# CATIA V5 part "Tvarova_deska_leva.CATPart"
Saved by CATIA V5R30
Part number: Tvarova_deska_leva
Definition: F 50_346446_46_1730_1
Nomenclature: F 50_346446_46_1730_1
Source: Unknown
Description: PART--DESC
Bounding box of the stored display mesh (mm): x -223 to 223, y -173 to 173, z -92 to 0
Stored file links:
  E:\Bakalarka\Model\Forma_v7\Tvarova_deska_leva.CATPart
  E:\Bakalarka\Model\Forma_v7\Vyhazovaci_cast.CATProduct
  E:\Bakalarka\Model\Sestava_formy_1\Forma_Vyhazovaci_cast.CATPart
  E:\Bakalarka\Model\Chyba catie 2\Forma_Vyhazovaci_cast.CATPart
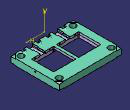
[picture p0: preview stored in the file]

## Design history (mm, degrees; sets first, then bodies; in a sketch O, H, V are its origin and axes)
Body1 "MANIFOLD_SOLID_BREP #4123" (main body)
  Solid1: solid without history
  DatumCurve1 to DatumCurve16
  Sketch1 on face of Solid1, origin (0, 0, -46), H (1, 0, 0), V (0, 1, 0)
    projected line E1 (170, 75) -> (170, -75) from edge of DatumCurve1
    projected arc E2 centre (165, -75) radius 5 from (165, -80) to (170, -75) ccw from edge of DatumCurve2
    projected line E3 (165, -80) -> (15, -80) from edge of DatumCurve3
    projected arc E4 centre (15, -75) radius 5 from (10, -75) to (15, -80) ccw from edge of DatumCurve4
    projected line E5 (10, -75) -> (10, 75) from edge of DatumCurve5
    projected arc E6 centre (15, 75) radius 5 from (15, 80) to (10, 75) ccw from edge of DatumCurve6
    projected line E7 (15, 80) -> (165, 80) from edge of DatumCurve7
    projected arc E8 centre (165, 75) radius 5 from (170, 75) to (165, 80) ccw from edge of DatumCurve8
    projected line E9 (-165, 80) -> (-15, 80) from edge of DatumCurve9
    projected arc E10 centre (-15, 75) radius 5 from (-10, 75) to (-15, 80) ccw from edge of DatumCurve10
    projected line E11 (-10, 75) -> (-10, -75) from edge of DatumCurve11
    projected arc E12 centre (-15, -75) radius 5 from (-15, -80) to (-10, -75) ccw from edge of DatumCurve12
    projected line E13 (-15, -80) -> (-165, -80) from edge of DatumCurve13
    projected arc E14 centre (-165, -75) radius 5 from (-170, -75) to (-165, -80) ccw from edge of DatumCurve14
    projected line E15 (-170, -75) -> (-170, 75) from edge of DatumCurve15
    projected arc E16 centre (-165, 75) radius 5 from (-165, 80) to (-170, 75) ccw from edge of DatumCurve16
  Pocket1: profile Sketch1, direction (0, 0, -1), length 16
  DatumSurface1
  DatumSurface2
  DatumCurve17 to DatumCurve30
  Sketch2 on face of Solid1, origin (0, 0, -92), H (1, 0, 0), V (0, -1, 0)
    projected arc E1 centre (5, -85) radius 5 from (0, -85) to (5, -90) ccw from edge of DatumCurve17
    projected line E2 (5, -90) -> (175, -90) from edge of DatumCurve18
    projected arc E3 centre (175, -85) radius 5 from (175, -90) to (180, -85) ccw from edge of DatumCurve19
    projected line E4 (180, -85) -> (180, 85) from edge of DatumCurve20
    projected arc E5 centre (175, 85) radius 5 from (180, 85) to (175, 90) ccw from edge of DatumCurve21
    projected line E6 (175, 90) -> (5, 90) from edge of DatumCurve22
    projected arc E7 centre (5, 85) radius 5 from (5, 90) to (0, 85) ccw from edge of DatumCurve23
    projected arc E8 centre (-5, 85) radius 5 from (0, 85) to (-5, 90) ccw from edge of DatumCurve24
    projected line E9 (-5, 90) -> (-175, 90) from edge of DatumCurve25
    projected arc E10 centre (-175, 85) radius 5 from (-175, 90) to (-180, 85) ccw from edge of DatumCurve26
    projected line E11 (-180, 85) -> (-180, -85) from edge of DatumCurve27
    projected arc E12 centre (-175, -85) radius 5 from (-180, -85) to (-175, -90) ccw from edge of DatumCurve28
    projected line E13 (-175, -90) -> (-5, -90) from edge of DatumCurve29
    projected arc E14 centre (-5, -85) radius 5 from (-5, -90) to (0, -85) ccw from edge of DatumCurve30
  Pocket2: profile Sketch2, direction (0, 0, 1), length 30
  Fillet1: radius 1, on edge [face of Pocket2 from Sketch2.E1 | face of Pocket2 from Sketch2.E14]; edge [face of Pocket2 from Sketch2.E8 | face of Pocket2 from Sketch2.E7]
  Body2 "Result of __DrillHole"
    Solid2: linked copy from another document
  Assemble1 "DrillHoleEjector_E1710_2.1": tool Body2
  Body3 "Result of __DrillHole"
    Solid3: linked copy from another document
  Assemble2 "DrillHoleEjector_E1710_3.1": tool Body3
  Body4 "Result of __DrillHole"
    Solid4: linked copy from another document
  Assemble3 "DrillHoleEjector_E1710_4.1": tool Body4
  Body5 "Result of __DrillHole"
    Solid5: linked copy from another document
  Assemble4 "DrillHoleEjector_E1710_5.1": tool Body5
  Body6 "Result of __DrillHole"
    Solid6: linked copy from another document
  Assemble5 "DrillHoleEjector_E1710_6.1": tool Body6
  Body7 "Result of __DrillHole"
    Solid7: linked copy from another document
  Assemble6 "DrillHoleEjector_E1710_1.1": tool Body7
  Body8 "Result of __DrillHole"
    Solid8: linked copy from another document
  Assemble7 "DrillHoleEjector_E1710_13.1": tool Body8
  Body9 "Result of __DrillHole"
    Solid9: linked copy from another document
  Assemble8 "DrillHoleEjector_E1710_14.1": tool Body9
  Body10 "Result of __DrillHole"
    Solid10: linked copy from another document
  Assemble9 "DrillHoleEjector_E1710_15.1": tool Body10
  Body11 "Result of __DrillHole"
    Solid11: linked copy from another document
  Assemble10 "DrillHoleEjector_E1710_16.1": tool Body11
  Body12 "Result of __DrillHole"
    Solid12: linked copy from another document
  Assemble11 "DrillHoleEjector_E1710_17.1": tool Body12
  Body13 "Result of __DrillHole"
    Solid13: linked copy from another document
  Assemble12 "DrillHoleEjector_E1710_18.1": tool Body13
  Body14 "Result of __DrillHole"
    Solid14: linked copy from another document
  Assemble13 "DrillHoleEjector_E1710_19.1": tool Body14
  Body15 "Result of __DrillHole"
    Solid15: linked copy from another document
  Assemble14 "DrillHoleEjector_E1710_20.1": tool Body15
  Body16 "Result of __DrillHole"
    Solid16: linked copy from another document
  Assemble15 "DrillHoleEjector_E1710_21.1": tool Body16
  Body17 "Result of __DrillHole"
    Solid17: linked copy from another document
  Assemble16 "DrillHoleEjector_E1710_23.1": tool Body17
  Body18 "Result of __DrillHole"
    Solid18: linked copy from another document
  Assemble17 "DrillHoleEjector_E1710_24.1": tool Body18
  Body19 "Result of __DrillHole"
    Solid19: linked copy from another document
  Assemble18 "DrillHoleEjector_E1710_25.1": tool Body19
  Body20 "Result of __DrillHole"
    Solid20: linked copy from another document
  Assemble19 "DrillHoleEjector_E1710_26.1": tool Body20
  Body21 "Result of __DrillHole"
    Solid21: linked copy from another document
  Assemble20 "DrillHoleEjector_E1710_27.1": tool Body21
  Body22 "Result of __DrillHole"
    Solid22: linked copy from another document
  Assemble21 "DrillHoleEjector_E1710_28.1": tool Body22
  Body23 "Result of __DrillHole"
    Solid23: linked copy from another document
  Assemble22 "DrillHoleEjector_E1710_29.1": tool Body23
  DatumCurve31 to DatumCurve38
  DatumSurface3
  DatumCurve39
  DatumSurface4
  DatumCurve40 to DatumCurve42
  DatumSurface5
  DatumCurve43 to DatumCurve49
  DatumSurface6
  DatumCurve50 to DatumCurve53
  DatumSurface7
  DatumCurve54
  Sketch3 on face of DatumSurface7, origin (0, 0, -128), H (1, 0, 0), V (0, 1, 0)
    construction line L1 (90.0667, -159.3771) -> (90.0667, -123.0944)
    line L2 (82.0323, -159.3771) -> (82.0323, -123.0944)
    line L3 (98.1012, -123.0944) -> (98.1012, -159.3771)
    arc A1 centre (90.0667, -123.0944) radius 8.0344 from (82.0323, -123.0944) to (98.1012, -123.0944) cw
    arc A2 centre (90.0667, -159.3771) radius 8.0344 from (98.1012, -159.3771) to (82.0323, -159.3771) cw
    construction line L4 (-89.9571, -153.2014) -> (-89.9571, -123.4032)
    line L5 (-99.1963, -153.2014) -> (-99.1963, -123.4032)
    line L6 (-80.718, -123.4032) -> (-80.718, -153.2014)
    arc A3 centre (-89.9571, -123.4032) radius 9.2392 from (-99.1963, -123.4032) to (-80.718, -123.4032) cw
    arc A4 centre (-89.9571, -153.2014) radius 9.2392 from (-80.718, -153.2014) to (-99.1963, -153.2014) cw
    reference projected line E1 (223, 173) -> (223, -173) from edge of DatumCurve54
    distance L1 L2 = 8.0344
    distance L4 L5 = 9.2392
    distance L1 E1 = 132.9333
    vertical: L1 V, L4 V
    tangency: A1 L2, A2 L2, A1 L3, A2 L3, A3 L5, A4 L5, A3 L6, A4 L6
  DatumCurve55
  DatumCurve56
  DatumSurface8
  DatumCurve57 to DatumCurve76
  DatumSurface9
  DatumCurve77
  DatumSurface10 to DatumSurface13
  DatumCurve78 to DatumCurve81
  Body24 "MANIFOLD_SOLID_BREP #197"
    Solid24: solid without history
  Remove1: tool Body24
  DatumCurve82
  DatumCurve83
  Sketch4 on face of Solid1, origin (0, -173, 0), H (1, 0, 0), V (0, 0, 1)
    point P1 (143.5, -54)
    reference projected line E1 (-223, -46) -> (189, -46) from edge [face of Solid1 | face of Solid1]
    reference projected line E2 (223, -88) -> (223, -50) from edge [face of Solid1 | face of Solid1]
    distance P1 E1 = 8
    distance P1 E2 = 79.5
  DatumCurve84 to DatumCurve91
  Sketch5 on face of Solid1, origin (0, 0, -92), H (1, 0, 0), V (0, -1, 0)
    point P17 (140, 137)
    point P18 (-140, 137)
    point P19 (-140, -137)
    point P20 (140, -137)
    reference projected line E9 (223, -139) -> (223, 139) from edge [face of Solid1 | face of Solid1]
    reference projected line E10 (-189, -173) -> (189, -173) from edge [face of Solid1 | face of Solid1]
    reference projected line E11 (-223, 139) -> (-223, -139) from edge [face of Solid1 | face of Solid1]
    reference projected line E12 (189, 173) -> (-189, 173) from edge [face of Solid1 | face of Solid1]
    distance P20 E9 = 83
    distance P20 E10 = 36
    distance P19 E10 = 36
    distance P19 E11 = 83
    distance P18 E11 = 83
    distance P18 E12 = 36
    distance P17 E12 = 36
    distance P17 E9 = 83
  Sketch6 on face of Solid1, origin (143.5, -173, -54), H (1, 0, 0), V (0, 0, 1)
    point P1 (0, 0)
    reference projected point E1 (0, 0) from Sketch4.P1
    coincidence: E1 P1
  Hole1: placed by Sketch6, at (143.5, -173, -54) direction (0, 1, 0), diameter 10, depth 150, V-bottom angle 120
  DatumSurface14
  Sketch7 on face of Solid1, origin (0, -173, 0), H (1, 0, 0), V (0, 0, 1)
    point P1 (35, -54)
    point P2 (-36.5, -54)
    point P3 (-145, -54)
    reference projected line E1 (-223, -88) -> (-223, -46) from edge [face of Solid1 | face of Solid1]
    reference intersected curve E2 from face of DatumSurface14
    reference projected line E3 (-223, -46) -> (189, -46) from edge [face of Solid1 | face of Solid1]
    distance P3 E1 = 78
    distance P2 P3 = 108.5
    distance P3 E2 = 8
    distance P2 E3 = 8
    distance P1 E3 = 8
    distance P2 P1 = 71.5
  Sketch8 on face of Solid1, origin (35, -173, -54), H (1, 0, 0), V (0, 0, 1)
    point P1 (0, 0)
    reference projected point E1 (0, 0) from Sketch7.P1
    coincidence: E1 P1
  Hole2: placed by Sketch8, at (35, -173, -54) direction (0, 1, 0), diameter 10, depth 150, V-bottom angle 120
  Sketch9 on face of Solid1, origin (-36.5, -173, -54), H (1, 0, 0), V (0, 0, 1)
    point P1 (0, 0)
    reference projected point E1 (0, 0) from Sketch7.P2
    coincidence: E1 P1
  Hole3: placed by Sketch9, at (-36.5, -173, -54) direction (0, 1, 0), diameter 10, depth 150, V-bottom angle 120
  Sketch10 on face of Solid1, origin (-145, -173, -54), H (1, 0, 0), V (0, 0, 1)
    point P1 (0, 0)
    reference projected point E1 (0, 0) from Sketch7.P3
    coincidence: E1 P1
  Hole4: placed by Sketch10, at (-145, -173, -54) direction (0, 1, 0), diameter 10, depth 150, V-bottom angle 120
  Sketch11 on face of Solid1, origin (143.5, -173, -54), H (1, 0, 0), V (0, 0, 1)
    point P1 (0, 0)
    reference projected point E1 (0, 0) from Sketch4.P1
    coincidence: E1 P1
  Hole5: placed by Sketch11, at (143.5, -173, -54) direction (0, 1, 0), diameter 12.376, depth 12, V-bottom angle 120, threaded "M14x1.5", thread diameter 14, thread depth 10, pitch 1.5
  Sketch12 on face of Solid1, origin (35, -173, -54), H (1, 0, 0), V (0, 0, 1)
    point P1 (0, 0)
    reference projected point E1 (0, 0) from Sketch7.P1
    coincidence: E1 P1
  Hole6: placed by Sketch12, at (35, -173, -54) direction (0, 1, 0), diameter 12.376, depth 12, V-bottom angle 120, threaded "M14x1.5", thread diameter 14, thread depth 10, pitch 1.5
  Sketch13 on face of Solid1, origin (-36.5, -173, -54), H (1, 0, 0), V (0, 0, 1)
    point P1 (0, 0)
    reference projected point E1 (0, 0) from Sketch7.P2
    coincidence: E1 P1
  Hole7: placed by Sketch13, at (-36.5, -173, -54) direction (0, 1, 0), diameter 12.376, depth 12, V-bottom angle 120, threaded "M14x1.5", thread diameter 14, thread depth 10, pitch 1.5
  Sketch14 on face of Solid1, origin (-145, -173, -54), H (1, 0, 0), V (0, 0, 1)
    point P1 (0, 0)
    reference projected point E1 (0, 0) from Sketch7.P3
    coincidence: E1 P1
  Hole8: placed by Sketch14, at (-145, -173, -54) direction (0, 1, 0), diameter 12.376, depth 12, V-bottom angle 120, threaded "M14x1.5", thread diameter 14, thread depth 10, pitch 1.5
  DatumCurve92
  Sketch15 on face of Solid1, origin (0, -173, 0), H (1, 0, 0), V (0, 0, 1)
    arc A1 centre (143.5, -54) radius 12.5 from (131, -54) to (156, -54) ccw
    arc A2 centre (35, -54) radius 12.5 from (22.5, -54) to (47.5, -54) ccw
    arc A3 centre (-36.5, -54) radius 12.5 from (-49, -54) to (-24, -54) ccw
    arc A4 centre (-145.5, -54) radius 12.5 from (-158, -54) to (-133, -54) ccw
    reference projected line E1 (223, -88) -> (223, -50) from edge [face of Solid1 | face of Solid1]
    reference projected line E2 (189, -92) -> (-189, -92) from edge [face of Solid1 | face of Solid1]
    reference projected line E3 (-223, -92) -> (223, -92) from edge of DatumCurve92
    projected line E4 (-223, -46) -> (189, -46) from edge [face of Solid1 | face of Solid1]
    projected line E5 (-158, -46) -> (-133, -46) from edge [face of Solid1 | face of Solid1]
    projected line E6 (-49, -46) -> (-24, -46) from edge [face of Solid1 | face of Solid1]
    projected line E7 (22.5, -46) -> (47.5, -46) from edge [face of Solid1 | face of Solid1]
    projected line E8 (131, -46) -> (156, -46) from edge [face of Solid1 | face of Solid1]
    line L1 (156, -54) -> (156, -46)
    point P8 (156, -46)
    line L2 (131, -54) -> (131, -46)
    point P10 (131, -46)
    line L3 (47.5, -54) -> (47.5, -46)
    point P12 (47.5, -46)
    line L4 (22.5, -54) -> (22.5, -46)
    point P14 (22.5, -46)
    line L5 (-49, -54) -> (-49, -46)
    point P16 (-49, -46)
    line L6 (-24, -54) -> (-24, -46)
    point P18 (-24, -46)
    line L7 (-133, -54) -> (-133, -46)
    point P19 (-133, -54)
    point P20 (-133, -46)
    line L8 (-158, -54) -> (-158, -46)
    point P22 (-158, -46)
    point P23 (-133, -54)
    radius A4 = 12.5
    radius A3 = 12.5
    radius A2 = 12.5
    radius A1 = 12.5
    distance E1 A1 = 67
    distance A1 E2 = 25.5
    distance A2 A1 = 83.5
    distance A2 E2 = 25.5
    distance A3 A2 = 46.5
    distance A3 E2 = 25.5
    distance A4 A3 = 84
    distance A4 E3 = 50.5
    length L1 = 8
    length L2 = 8
    length L3 = 8
    length L4 = 8
    length L6 = 8
    length L5 = 8
    length L7 = 8
    length L8 = 8
    coincidence: P8 E4, P10 E4, P12 E4, P14 E4, P16 E4, P18 E4, P19 A4, P20 E4, P22 E4, L7 P23
    tangency: L1 A1, L2 A1, L3 A2, L4 A2, L5 A3, L6 A3, L7 A4, L8 A4
  Pocket3: profile Sketch15, direction (0, 1, 0), length 18
  Sketch16 on end face of Pocket3, origin (0, -155, 0), H (1, 0, 0), V (0, 0, 1)
    projected point E1 (-145, -54) from Sketch7.P3
    projected point E2 (-36.5, -54) from Sketch7.P2
    projected point E3 (35, -54) from Sketch7.P1
    projected point E4 (143.5, -54) from Sketch4.P1
  Sketch17 on end face of Pocket3, origin (143.5, -155, -54), H (1, 0, 0), V (0, 0, 1)
    point P1 (0, 0)
    reference projected point E1 (0, 0) from vertex of Sketch16.E4
    coincidence: E1 P1
  Hole9: placed by Sketch17, at (143.5, -155, -54) direction (0, 1, 0), diameter 12.376, depth 12, V-bottom angle 120, threaded "M14x1.5", thread diameter 14, thread depth 10, pitch 1.5
  Sketch18 on end face of Pocket3, origin (35, -155, -54), H (1, 0, 0), V (0, 0, 1)
    point P1 (0, 0)
    reference projected point E1 (0, 0) from Sketch7.P1
    coincidence: E1 P1
  Hole10: placed by Sketch18, at (35, -155, -54) direction (0, 1, 0), diameter 12.376, depth 12, V-bottom angle 120, threaded "M14x1.5", thread diameter 14, thread depth 10, pitch 1.5
  Sketch19 on end face of Pocket3, origin (-36.5, -155, -54), H (1, 0, 0), V (0, 0, 1)
    point P1 (0, 0)
    reference projected point E1 (0, 0) from vertex of Sketch16.E2
    coincidence: E1 P1
  Hole11: placed by Sketch19, at (-36.5, -155, -54) direction (0, 1, 0), diameter 12.376, depth 12, V-bottom angle 120, threaded "M14x1.5", thread diameter 14, thread depth 10, pitch 1.5
  Sketch20 on end face of Pocket3, origin (-145, -155, -54), H (1, 0, 0), V (0, 0, 1)
    point P1 (0, 0)
    reference projected point E1 (0, 0) from vertex of Sketch16.E1
    coincidence: E1 P1
  Hole12: placed by Sketch20, at (-145, -155, -54) direction (0, 1, 0), diameter 12.376, depth 12, V-bottom angle 120, threaded "M14x1.5", thread diameter 14, thread depth 10, pitch 1.5
  Plane1: type Offset, RefPlane face of Solid1, Offset 23
  DatumCurve93 to DatumCurve95
  Sketch21 on face of Solid1, origin (0, 0, -46), H (1, 0, 0), V (0, 1, 0)
    projected line E1 (-223, -139) -> (-223, -173) from edge of DatumCurve93
    projected line E2 (-223, -173) -> (-189, -173) from edge of DatumCurve94
    projected line E3 (-223, -139) -> (-189, -173) from edge of DatumCurve95
  Pocket4: profile Sketch21, direction (0, 0, -1), length 4
  DatumPoint1
  Sketch22 on face of Solid1, origin (223, 0, -58), H (0, 1, 0), V (0, 0, 1)
    point P1 (0, 0)
    reference projected point E1 (0, 0) from vertex of DatumPoint1
    coincidence: E1 P1
  Hole13: placed by Sketch22, at (223, 0, -58) direction (-1, 0, 0), diameter 10.106, depth 26, V-bottom angle 120, threaded "M12", thread diameter 12, thread depth 20, pitch 1.75
  DatumSurface15
  Sketch23 on face of Solid1, origin (0, 0, -46), H (1, 0, 0), V (0, 1, 0)
  Pocket5: profile Sketch23, direction (0, 0, -1), length 4
  DatumCurve96
  Point1: stored without definition
  Point2: stored without definition
  Sketch24 on face of Solid1, origin (0, -173, 0), H (1, 0, 0), V (0, 0, 1)
    line L1 (-74.5, -46) -> (-74.5, -58)
    line L2 (-74.5, -58) -> (-70, -58)
    line L3 (-70, -58) -> (-70, -66)
    line L4 (-70, -66) -> (-111, -66)
    line L5 (-111, -66) -> (-111, -58)
    point P6 (-111, -58)
    line L6 (-111, -58) -> (-106.5, -58)
    line L7 (-106.5, -58) -> (-106.5, -46)
    line L8 (-106.5, -46) -> (-74.5, -46)
    reference projected line E1 through (-90.5, 0) direction (0, -1) from edge of DatumCurve96
    reference projected line E2 (-223, -46) -> (189, -46) from edge [face of Solid1 | face of Solid1]
    line L9 (69, -66) -> (110, -66)
    line L10 (110, -66) -> (110, -58)
    line L11 (110, -58) -> (105.5, -58)
    line L12 (105.5, -58) -> (105.5, -46)
    line L13 (105.5, -46) -> (73.5, -46)
    line L14 (73.5, -46) -> (73.5, -58)
    point P15 (73.5, -58)
    line L15 (73.5, -58) -> (69, -58)
    line L16 (69, -58) -> (69, -66)
    reference projected point E3 (89.5, -57) from vertex of Point1
    reference projected point E4 (89.5, -57) from vertex of Point2
    distance L3 E1 = 20.5
    distance L1 L3 = 4.5
    distance L8 E2 = 0
    distance L2 L8 = 12
    distance L4 L8 = 20
    distance L5 L3 = 41
    distance L7 L1 = 32
    distance L13 E2 = 0
    distance L12 E3 = 16
    distance L10 E4 = 20.5
    distance L9 L13 = 20
    distance L11 L9 = 8
    distance L16 L10 = 41
    distance L14 L16 = 4.5
    vertical: L1 V, L3 V, L5 V, L7 V, L10 V, L12 V, L14 V, L16 V
    horizontal: L2 H, L4 H, L6 H, L8 H, L9 H, L11 H, L13 H, L15 H
    coincidence: P6 L2, P15 L11
  Pocket6: profile Sketch24, direction (0, 1, 0), through (limit type 6), opposite side length 3
  DatumSurface16
  Sketch25 on face of Solid1, origin (0, -173, 0), H (1, 0, 0), V (0, 0, 1)
    line L1 (69, -46) -> (110, -46)
    line L2 (110, -46) -> (110, -58)
    line L3 (110, -58) -> (69, -58)
    line L4 (69, -58) -> (69, -46)
    line L5 (-111, -46) -> (-70, -46)
    line L6 (-70, -46) -> (-70, -58)
    line L7 (-70, -58) -> (-111, -58)
    line L8 (-111, -58) -> (-111, -46)
    reference projected line E1 (-223, -46) -> (189, -46) from edge [face of Solid1 | face of Solid1]
    reference projected line E2 (73.5, -46) -> (73.5, -58) from edge [face of Solid1 | face of Pocket6 from Sketch24.L14]
    reference projected line E3 (105.5, -58) -> (105.5, -46) from edge [face of Solid1 | face of Pocket6 from Sketch24.L12]
    reference projected line E4 (-74.5, -58) -> (-74.5, -46) from edge [face of Solid1 | face of Pocket6 from Sketch24.L1]
    reference projected line E5 (-106.5, -46) -> (-106.5, -58) from edge [face of Solid1 | face of Pocket6 from Sketch24.L7]
    distance L1 E1 = 0
    distance L4 E2 = 4.5
    distance L2 E3 = 4.5
    distance L1 L3 = 12
    distance L5 E1 = 0
    distance L6 E4 = 4.5
    distance L8 E5 = 4.5
    distance L7 L5 = 12
    horizontal: L1 H, L3 H, L5 H, L7 H
    vertical: L2 V, L4 V, L6 V, L8 V
  Pocket7: profile Sketch25, direction (0, 1, 0), length 43
  Fillet2: radius 0.5, on edge [face of Pocket6 from Sketch24.L9 | face of Pocket7]; edge [face of Pocket7 | face of Pocket6 from Sketch24.L15]; edge [face of Pocket6 from Sketch24.L15 | end face of Pocket7]; edge [face of Pocket6 from Sketch24.L15 | face of Pocket6 from Sketch24.L14]; edge [end face of Pocket7 | face of Pocket6 from Sketch24.L14]; edge [face of Pocket7 | end face of Pocket7] (x4); edge [face of Pocket6 from Sketch24.L11 | face of Pocket7]; edge [face of Pocket6 from Sketch24.L11 | end face of Pocket7]; edge [end face of Pocket7 | face of Pocket6 from Sketch24.L12]; edge [face of Pocket6 from Sketch24.L12 | face of Pocket6 from Sketch24.L11]; edge [face of Pocket7 | face of Pocket6 from Sketch24.L9]; edge [face of Pocket6 from Sketch24.L1 | face of Pocket6 from Sketch24.L2]; edge [face of Pocket6 from Sketch24.L2 | end face of Pocket7]; edge [face of Pocket6 from Sketch24.L2 | face of Pocket7]; edge [face of Pocket6 from Sketch24.L1 | end face of Pocket7]; edge [face of Pocket7 | face of Pocket6 from Sketch24.L6]; edge [face of Pocket6 from Sketch24.L6 | face of Pocket6 from Sketch24.L7]; edge [face of Pocket6 from Sketch24.L6 | end face of Pocket7]; edge [face of Pocket6 from Sketch24.L7 | end face of Pocket7]; edge [face of Pocket6 from Sketch24.L4 | face of Pocket7]; edge [face of Pocket7 | face of Pocket6 from Sketch24.L4]
  Chamfer1: length 1, second length 1, on edge [face of Solid1 | face of Pocket6 from Sketch24.L4]; edge [face of Solid1 | face of Pocket7] (x3); edge [face of Solid1 | end face of Pocket7]; edge [face of Pocket7 | face of Solid1]
  Chamfer2: length 1, second length 1, on edge [face of Pocket6 from Sketch24.L14 | face of Pocket1 from Sketch1.E3]; edge [face of Pocket1 from Sketch1.E3 | face of Pocket6 from Sketch24.L12]; edge [face of Pocket6 from Sketch24.L7 | face of Pocket1 from Sketch1.E13]; edge [face of Pocket1 from Sketch1.E13 | face of Pocket6 from Sketch24.L1]
  Body25 "E 1032_12x120"
    Solid25: solid without history
  Remove2: tool Body25
  Body26 "E 1032_12x120"
    Solid26: solid without history
  Remove3: tool Body26
  Sketch26 on face of Solid26, origin (0, -39.4769, -121.4975), H (-1, 0, 0), V (0, -0.9511, 0.309)
    projected arc E1 centre (90.5, 101.0158) radius 6 from (90.5, 95.0158) to (90.5, 107.0158) ccw from edge [face of Solid25 | face of Pocket6 from Sketch24.L4]
    projected arc E2 centre (90.5, 101.0158) radius 6 from (90.5, 107.0158) to (90.5, 95.0158) ccw from edge [face of Solid25 | face of Pocket6 from Sketch24.L4]
    projected arc E3 centre (-89.5, 101.0158) radius 6 from (-89.5, 95.0158) to (-89.5, 107.0158) ccw from edge [face of Solid26 | face of Pocket6 from Sketch24.L9]
    projected arc E4 centre (-89.5, 101.0158) radius 6 from (-89.5, 107.0158) to (-89.5, 95.0158) ccw from edge [face of Solid26 | face of Pocket6 from Sketch24.L9]
  Pocket8: profile Sketch26, direction (0, -0.309, -0.9511), length 43, opposite side length 10
  DatumCurve97 to DatumCurve100
  Sketch27 on face of Pocket6 from Sketch24.L4, origin (0, 0, -66), H (1, 0, 0), V (0, 1, 0)
    reference projected arc E1 centre (-90.5, -117.1573) radius 3.25 from (-93.75, -117.1573) to (-87.25, -117.1573) ccw from edge of DatumCurve97
    reference projected arc E3 centre (89.5, -117.1573) radius 3.25 from (86.25, -117.1573) to (92.75, -117.1573) ccw from edge of DatumCurve99
    point P9 (89.5, -117.1573)
    point P10 (-90.5, -117.1573)
    concentricity: P9 E3, P10 E1
  Sketch28 on face of Pocket6 from Sketch24.L9, origin (89.5, -117.1573, -66), H (1, 0, 0), V (0, 1, 0)
    point P1 (0, 0)
    reference projected point E1 (0, 0) from Sketch27.P9
    coincidence: E1 P1
  Hole14: placed by Sketch28, at (89.5, -117.1573, -66) direction (0, 0, -1), diameter 6, depth 7, V-bottom angle 120, counterbore diameter 6.5, counterbore depth 1
  Sketch29 on face of Pocket6 from Sketch24.L4, origin (-90.5, -117.1573, -66), H (1, 0, 0), V (0, 1, 0)
    point P1 (0, 0)
    reference projected point E1 (0, 0) from Sketch27.P10
    coincidence: E1 P1
  Hole15: placed by Sketch29, at (-90.5, -117.1573, -66) direction (0, 0, -1), diameter 6, depth 7, V-bottom angle 120, counterbore diameter 6.5, counterbore depth 1
  DatumCurve101
  Sketch30 on face of Solid1, origin (0, -173, 0), H (1, 0, 0), V (0, 0, 1)
    line L1 (111, -67) -> (68, -67)
    line L2 (-69, -67) -> (-112, -67)
    projected line E1 (106, -58) -> (109.5, -58) from edge [face of Pocket6 from Sketch24.L11 | face of Fillet2]
    projected line E2 (105.5, -57.5) -> (105.5, -47) from edge [face of Fillet2 | face of Pocket6 from Sketch24.L12]
    projected line E3 (73.5, -47) -> (73.5, -57.5) from edge [face of Fillet2 | face of Pocket6 from Sketch24.L14]
    projected line E4 (69.5, -58) -> (73, -58) from edge [face of Pocket6 from Sketch24.L15 | face of Fillet2]
    projected arc E5 centre (106, -57.5) radius 0.5 from (105.5, -57.5) to (106, -58) ccw from edge [face of Fillet2 | face of Fillet2]
    projected line E6 (69, -65.5) -> (69, -47) from edge [face of Pocket7 | face of Chamfer1]
    projected arc E7 centre (73, -57.5) radius 0.5 from (73, -58) to (73.5, -57.5) ccw from edge [face of Fillet2 | face of Fillet2]
    projected line E8 (-74.5, -47) -> (-74.5, -57.5) from edge [face of Pocket6 from Sketch24.L1 | face of Fillet2]
    projected line E9 (-74, -58) -> (-70.5, -58) from edge [face of Pocket6 from Sketch24.L2 | face of Fillet2]
    projected arc E10 centre (-74, -57.5) radius 0.5 from (-74.5, -57.5) to (-74, -58) ccw from edge [face of Fillet2 | face of Fillet2]
    projected line E11 (-111, -47) -> (-111, -65.5) from edge [face of Chamfer1 | face of Pocket7]
    projected line E12 (-110.5, -58) -> (-107, -58) from edge [face of Pocket6 from Sketch24.L6 | face of Fillet2]
    projected arc E13 centre (-107, -57.5) radius 0.5 from (-107, -58) to (-106.5, -57.5) ccw from edge [face of Fillet2 | face of Fillet2]
    projected line E14 (-106.5, -57.5) -> (-106.5, -47) from edge [face of Pocket6 from Sketch24.L7 | face of Fillet2]
    line L3 (-74.5, -47) -> (-106.5, -47)
    line L4 (111, -67) -> (111, -58)
    point P33 (111, -58)
    line L5 (111, -58) -> (109.5, -58)
    line L6 (69.5, -58) -> (68, -58)
    line L7 (68, -58) -> (68, -67)
    line L8 (-69, -67) -> (-69, -58)
    point P35 (-69, -58)
    line L9 (-70.5, -58) -> (-69, -58)
    line L10 (-110.5, -58) -> (-112, -58)
    line L11 (-112, -58) -> (-112, -67)
    reference projected line E15 (-110.5, -66) -> (-70.5, -66) from edge [face of Chamfer1 | face of Pocket6 from Sketch24.L4]
    reference projected line E16 (-70, -65.5) -> (-70, -47) from edge [face of Chamfer1 | face of Pocket7]
    reference projected line E17 (109.5, -66) -> (69.5, -66) from edge [face of Pocket6 from Sketch24.L9 | face of Chamfer1]
    reference projected line E18 (110, -47) -> (110, -65.5) from edge [face of Pocket7 | face of Chamfer1]
    line L12 (73.5, -47) -> (105.3145, -47)
    line L13 (105.3145, -47) -> (105.5, -47)
    distance L2 E15 = 1
    distance L11 E11 = 1
    distance L8 E16 = 1
    distance L7 E6 = 1
    distance L1 E17 = 1
    distance L4 E18 = 1
    horizontal: L1 H, L2 H, L3 H, L5 H, L9 H, L12 H, L13 H
    coincidence: P33 E1, P35 E9
    vertical: L4 V, L7 V, L8 V, L11 V
    tangency: L6 E7, L10 E13
  Pocket9: profile Sketch30, direction (0, 1, 0), length 100
  Chamfer3: length 0.5, angle 45, on edge [face of Pocket9 | face of Pocket9 from Sketch30.L11]; edge [face of Pocket9 from Sketch30.L8 | face of Pocket9]
  Fillet3: radius 0.5, on face of Pocket9 from Sketch30.L9
  Fillet4: radius 0.5, on face of Pocket9 from Sketch30.L10
  Fillet5: radius 0.5, on face of Pocket9 from Sketch30.L5
  Fillet6: radius 0.5, on edge [face of Pocket7 | face of Pocket9 from Sketch30.L6]; edge [face of Pocket9 from Sketch30.L7 | face of Pocket9 from Sketch30.L6]; face of Pocket9 from Sketch30.L6
  Sketch31 on face of Solid1, origin (0, 0, -92), H (1, 0, 0), V (0, -1, 0)
    projected arc E1 centre (-140, 137) radius 8 from (-132, 137) to (-148, 137) ccw from edge [face of Solid1 | face of Solid1]
    projected arc E2 centre (-140, 137) radius 8 from (-148, 137) to (-132, 137) ccw from edge [face of Solid1 | face of Solid1]
    projected arc E3 centre (140, 137) radius 8 from (148, 137) to (132, 137) ccw from edge [face of Solid1 | face of Solid1]
    projected arc E4 centre (140, 137) radius 8 from (132, 137) to (148, 137) ccw from edge [face of Solid1 | face of Solid1]
  Sketch32 on face of Solid1, origin (0, 0, -92), H (1, 0, 0), V (0, -1, 0)
    reference projected arc E1 centre (-140, 137) radius 8 from (-132, 137) to (-148, 137) ccw from Sketch31.E1
    reference projected arc E3 centre (140, 137) radius 8 from (148, 137) to (132, 137) ccw from Sketch31.E3
    point P9 (-140, 137)
    point P10 (140, 137)
    concentricity: P9 E1, P10 E3
  Pad1: profile Sketch31, direction (0, 0, 1), length 34
  Sketch33 on face of Pad1, origin (-140, -137, -92), H (1, 0, 0), V (0, -1, 0)
    point P1 (0, 0)
    reference projected point E1 (0, 0) from Sketch32.P9
    coincidence: E1 P1
  Hole16: placed by Sketch33, at (-140, -137, -92) direction (0, 0, 1), diameter 13.835, depth 24, V-bottom angle 120, threaded "M16", thread diameter 16, thread depth 20, pitch 2
  Sketch34 on face of Pad1, origin (140, -137, -92), H (1, 0, 0), V (0, -1, 0)
    point P1 (0, 0)
    reference projected point E1 (0, 0) from Sketch32.P10
    coincidence: E1 P1
  Hole17: placed by Sketch34, at (140, -137, -92) direction (0, 0, 1), diameter 13.835, depth 24, V-bottom angle 120, threaded "M16", thread diameter 16, thread depth 20, pitch 2
  Sketch35 on end face of Pocket3, origin (0, -155, 0), H (1, 0, 0), V (0, 0, 1)
    reference projected circle E1 centre (143.5, -54) radius 6.188 from edge [end face of Pocket3 | face of Hole9]
    reference projected circle E2 centre (-145, -54) radius 6.188 from edge [end face of Pocket3 | face of Hole12]
    point P1 (-145, -54)
    point P2 (143.5, -54)
    concentricity: P1 E2, P2 E1
  Sketch36 on end face of Pocket3, origin (143.5, -155, -54), H (1, 0, 0), V (0, 0, 1)
    point P1 (0, 0)
    reference projected point E1 (0, 0) from Sketch35.P2
    coincidence: E1 P1
  Hole18: placed by Sketch36, at (143.5, -155, -54) direction (0, 1, 0), diameter 12.376, depth 12, V-bottom angle 120, threaded "M14x1.5", thread diameter 14, thread depth 12, pitch 1.5
  Sketch37 on end face of Pocket3, origin (-145, -155, -54), H (1, 0, 0), V (0, 0, 1)
    point P1 (0, 0)
    reference projected point E1 (0, 0) from Sketch35.P1
    coincidence: E1 P1
  Hole19: placed by Sketch37, at (-145, -155, -54) direction (0, 1, 0), diameter 12.376, depth 12, V-bottom angle 120, threaded "M14x1.5", thread diameter 14, thread depth 12, pitch 1.5
  Sketch38 on end face of Pocket3, origin (-145, -155, -54), H (1, 0, 0), V (0, 0, 1)
    point P1 (0, 0)
    reference projected point E1 (0, 0) from Sketch35.P1
    coincidence: E1 P1
  Hole20: placed by Sketch38, at (-145, -155, -54) direction (0, 1, 0), diameter 10, depth 30, V-bottom angle 120
  Sketch39 on end face of Pocket3, origin (143.5, -155, -54), H (1, 0, 0), V (0, 0, 1)
    point P1 (0, 0)
    reference projected point E1 (0, 0) from Sketch35.P2
    coincidence: E1 P1
  Hole21: placed by Sketch39, at (143.5, -155, -54) direction (0, 1, 0), diameter 10, depth 30, V-bottom angle 120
